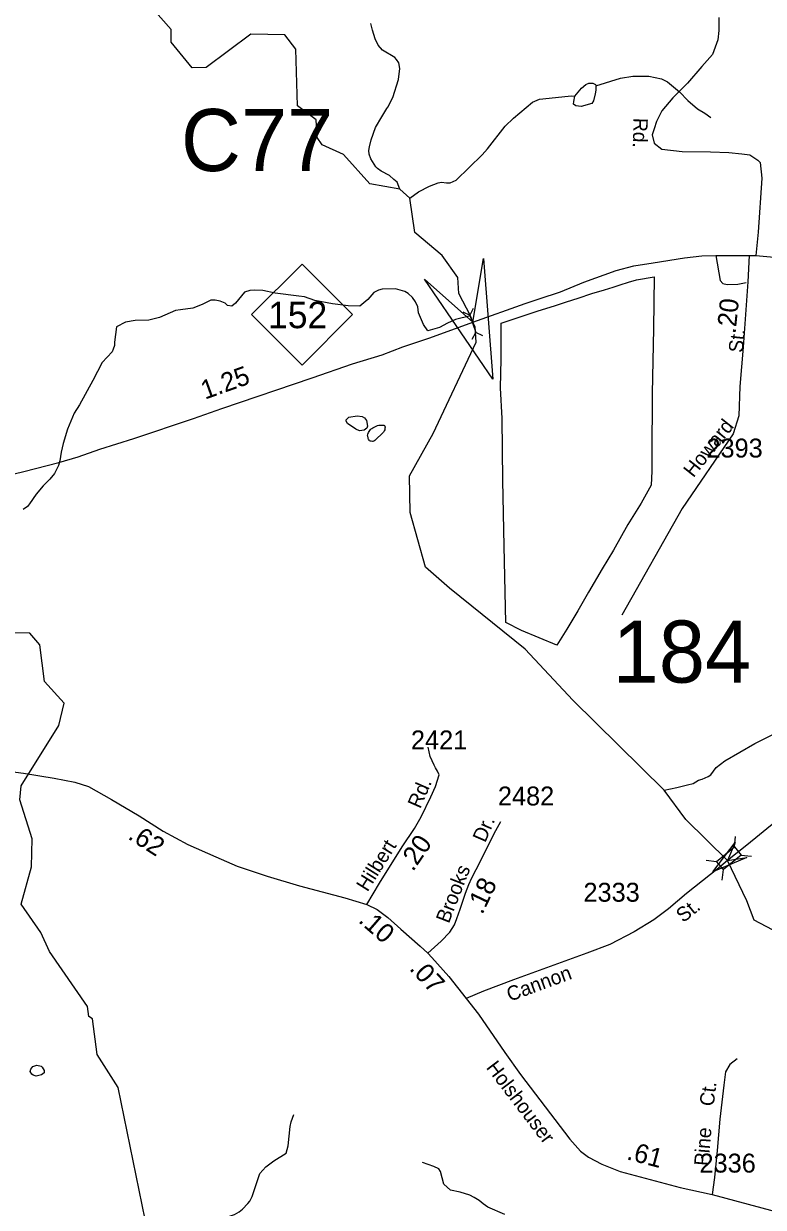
# Model space of a CAD drawing. Extents: x 1473865 to 1648260, y 639067 to 773536.
# Drawn here: x 1572849 to 1577734, y 652286 to 660104 of the extents above; entities that cross this region are included whole.
import ezdxf

# ---------------------------------------------------------------- set-up
doc = ezdxf.new("R2010")
doc.units = 0
for name, color, linetype in [('Exist Boundary Political City Limit New', 7, 'Continuous'), ('Exist Hydrographic Creek Single Shore', 7, 'Continuous'), ('Exist Hydrographic Misc Water Feature', 7, 'Continuous'), ('Exist Road Non-System Type 51', 7, 'Continuous'), ('Exist Road Non-System Type 51 Label', 7, 'Continuous'), ('Exist Road Primary NC Attributed', 7, 'Continuous'), ('Exist Road Primary NC Service Mileage Hundredths English Label', 7, 'Continuous'), ('Exist Road Primary NC Shield CELL', 7, 'Continuous'), ('Exist Road Primary NC Shield Number Label', 7, 'Continuous'), ('Exist Road Secondary Mileage Hundredths English Label', 7, 'Continuous'), ('Exist Road Secondary Structure Culvert Attributed CELL', 7, 'Continuous'), ('Exist Road Secondary Structure Culvert CELL', 7, 'Continuous'), ('Exist Road Secondary Structure Culvert Number Label', 7, 'Continuous'), ('Exist Road Secondary Structure Standard Bridge Attributed CELL', 7, 'Continuous'), ('Exist Road Secondary Structure Standard Bridge CELL', 7, 'Continuous'), ('Exist Road Secondary Structure Standard Bridge Number Label', 7, 'Continuous'), ('Exist Road Secondary Type 51 Attributed', 7, 'Continuous'), ('Exist Road Secondary Type 51 Label', 7, 'Continuous'), ('Exist Road Secondary Type 51 Number Label', 7, 'Continuous'), ('Map Preparation Boundary City Limit Buffer Line', 7, 'Continuous')]:
    doc.layers.add(name, color=color, linetype=linetype)

msp = doc.modelspace()

# ---------------------------------------------------------------- linework, layer by layer
at = {"layer": 'Exist Boundary Political City Limit New'}
msp.add_lwpolyline([(1576436.5, 656103.4), (1576371.1, 655999.6), (1576136.9, 656095.7), (1576033.1, 656149.5), (1576021.6, 656653), (1576014, 657087.4), (1576010.1, 657494.8), (1575998.6, 657698.5), (1576002.4, 657886.9), (1576002.4, 658125.1), (1576107.4, 658161.8), (1576247.6, 658206), (1576354.2, 658241.1), (1576433.5, 658265.7), (1576510.8, 658289.9), (1576601.6, 658320.5), (1576684.8, 658345.2), (1576741.8, 658362.4), (1576788.8, 658379.4), (1576844.2, 658396.6), (1576895.8, 658412.5), (1577012.6, 658432.6), (1577008.8, 658090.6), (1577001, 657660.1), (1576997.2, 657244.9), (1576997.2, 657148.9), (1576993.4, 657056.6), (1576928.1, 656937.4), (1576839.8, 656795.2), (1576743.8, 656626.1), (1576670.8, 656503.1), (1576578.5, 656349.4), (1576509.4, 656226.4), (1576436.5, 656103.4)], dxfattribs=at)
at = {"layer": 'Exist Hydrographic Creek Single Shore'}
msp.add_lwpolyline([(1577962.3, 654029.9), (1577674.3, 654182.5), (1577624.4, 654309.2), (1577496.8, 654576.7), (1577223.2, 654846.6), (1577078.6, 655040.2), (1576476.4, 655635.4), (1576161.4, 655973.1), (1575661, 656375.3), (1575503.4, 656513.3), (1575402.3, 656874.9), (1575398.3, 657117.9), (1575553.8, 657395.9), (1575837.4, 658000.3), (1575831.5, 658101.1), (1575814.9, 658133.1), (1575800.7, 658174.7), (1575723.3, 658322.5), (1575716.8, 658427.9), (1575613.1, 658573.2), (1575432.3, 658724.5), (1575398.4, 658950.1), (1575333.4, 659009.8), (1575134.4, 659046.7), (1574961.4, 659240.6), (1574821.4, 659302.5), (1574788.4, 659352.4), (1574781.4, 659467.4), (1574658.4, 659561.8), (1574646.4, 659936.2), (1574573.4, 660029.6), (1574348.4, 660034.2), (1574053.4, 659813.7), (1573961.4, 659812.2), (1573822.4, 659982.4), (1573823.4, 660064.5), (1573585.4, 660335.1)], dxfattribs=at)
at = {"layer": 'Exist Hydrographic Misc Water Feature'}
for points in [[(1575333.4, 659009.8), (1575316.5, 659057.3), (1575294.7, 659073.5), (1575265.9, 659099.9), (1575210.2, 659128.6), (1575186.4, 659146.9), (1575174.5, 659159), (1575141.1, 659211.4), (1575131.4, 659241.5), (1575129.6, 659265.6), (1575132, 659289.5), (1575144.5, 659337.4), (1575173.4, 659417), (1575214.2, 659488.6), (1575246.8, 659544.2), (1575254.9, 659552.1), (1575287.6, 659615.7), (1575324.9, 659735.3), (1575333.8, 659807.2), (1575326.2, 659845.3), (1575312.4, 659867.4), (1575300.5, 659879.6), (1575219, 659928.6), (1575189.4, 659960.9), (1575169.8, 660003.1), (1575152.5, 660061.3), (1575142.9, 660105.5)], [(1576629, 659694.1), (1576791.6, 659744.2), (1576871.7, 659757.3), (1576977.8, 659756.5), (1577061.6, 659739.1), (1577101.4, 659719), (1577180.8, 659653.7), (1577236.1, 659597), (1577299.5, 659540.3), (1577347.3, 659511.7), (1577386.9, 659483.3)], [(1576629, 659694.1), (1576628.7, 659664.1), (1576624.3, 659640.1), (1576611.8, 659594.3), (1576601.7, 659576.4), (1576531.5, 659557.3), (1576495.5, 659561.7), (1576481.5, 659571.8), (1576481.7, 659589.8), (1576488.2, 659625.7)], [(1576488.2, 659625.7), (1576532.8, 659677.3), (1576563, 659702.9), (1576581.2, 659710.7), (1576609.2, 659710.3), (1576625.1, 659702.2), (1576629, 659694.1)], [(1575398.4, 658950.1), (1575456.8, 658993.7), (1575529.3, 659030.9), (1575585.5, 659052.2), (1575609.5, 659056), (1575641.5, 659051.5), (1575665.5, 659053.3), (1575705.7, 659070.8), (1575877.7, 659236.8), (1575912.1, 659276.4), (1576029.8, 659427.1), (1576084.3, 659478.5), (1576209.6, 659585), (1576255.9, 659604.5), (1576277.9, 659608.2), (1576464.2, 659628), (1576488.2, 659625.7)], [(1575800.7, 658174.7), (1575701.1, 658149.7), (1575647.8, 658126), (1575594.4, 658096.4), (1575518.6, 658075), (1575490.5, 658117), (1575456.1, 658193.1), (1575453, 658233.7), (1575437.5, 658265.5), (1575417, 658294.1), (1575387.3, 658322.5), (1575365.4, 658334.7), (1575305.7, 658351.4), (1575217.6, 658350.4), (1575193.5, 658342.7), (1575161.3, 658327.1), (1575121.8, 658280.8), (1575068.3, 658238.2), (1574992.2, 658239.1), (1574888.4, 658252.3), (1574772.5, 658275.6), (1574702.8, 658298.4), (1574666.8, 658304.8), (1574509, 658324.7), (1574429.2, 658341.6), (1574373.1, 658343.9), (1574342.4, 658340.5), (1574307.9, 658329.4), (1574247.9, 658257.5), (1574222.9, 658238.7), (1574194.3, 658242.9), (1574179.1, 658258.3), (1574146.8, 658270.1), (1574114.4, 658278.2), (1574085.7, 658278.5), (1574028.1, 658248.6), (1573966.7, 658224.5), (1573883.8, 658213.7), (1573851.4, 658208.3), (1573747, 658163.6), (1573674.7, 658144.4), (1573584.7, 658144.2), (1573521.5, 658133.2), (1573462.1, 658100.9), (1573449, 658001), (1573448.8, 657977), (1573440.5, 657953.1), (1573432.3, 657937.2), (1573367.5, 657865.9), (1573306.2, 657746.6), (1573217.9, 657585.3), (1573181.7, 657530.1), (1573148.8, 657452.4), (1573138.6, 657424.6), (1573109.4, 657330.9), (1573096.8, 657273.1), (1573088.2, 657217.1), (1573079.8, 657185.3), (1573051.3, 657133.6), (1573021.9, 657096.2), (1572977.3, 657051.4), (1572931.7, 656995), (1572887, 656931.5), (1572874.8, 656915.6), (1572844.5, 656895.9)], [(1575051.3, 657513.2), (1575084.2, 657509.9), (1575100.1, 657499.8), (1575113.9, 657481.6), (1575119.5, 657445.5), (1575115.4, 657431.6), (1575097.2, 657417.8), (1575067.2, 657414.1), (1575043.3, 657424.4), (1574987.6, 657463.1), (1574977.8, 657479.2), (1574977.9, 657487.2), (1574996.1, 657504.9), (1575051.3, 657513.2)], [(1575144.9, 657345.3), (1575138.6, 657346.8), (1575133.2, 657348.6), (1575129.9, 657351.8), (1575126.8, 657358.9), (1575124.8, 657363.7), (1575123.1, 657368.6), (1575121.4, 657378.4), (1575120.7, 657383.9), (1575121.5, 657391.3), (1575126, 657403.4), (1575140.6, 657423.6), (1575143.7, 657426.9), (1575147.8, 657429.7), (1575154.8, 657434.4), (1575168.5, 657441.9), (1575186.8, 657450.2), (1575194.1, 657452.3), (1575205.3, 657452.4), (1575226.6, 657451.4), (1575233, 657449.6), (1575234.9, 657444.3), (1575235.7, 657438.1), (1575235.2, 657432.8), (1575234.1, 657422.1), (1575230.7, 657413.3), (1575228.6, 657409.5), (1575226, 657406.4), (1575168.9, 657350), (1575162.1, 657345.8), (1575155.8, 657344.9), (1575152.6, 657344.7), (1575144.9, 657345.3)], [(1573651.3, 652206.5), (1573472.3, 653076.7), (1573333.3, 653296.2), (1573303.3, 653529.9), (1573278.3, 653546.8), (1573271.3, 653612.5), (1573018.3, 653975.4), (1572961.3, 654101.3), (1572831.3, 654287.8), (1572901.3, 654535.8), (1572904.3, 654719.6), (1572824.3, 654977.2), (1572833.3, 655068.9), (1573081.4, 655467.6), (1573116.3, 655614.6), (1572985.3, 655758.5), (1572955.4, 656002), (1572890.3, 656078.8), (1572773.4, 656081.2), (1572363.4, 655977.8), (1572231.3, 656046.1), (1571977.4, 656349.9)], [(1577078.6, 655040.2), (1577162.6, 655059.7), (1577233, 655077.3), (1577270.1, 655085.1), (1577306.5, 655107.8), (1577330.5, 655113.6), (1577370.7, 655131.1), (1577386.8, 655142.9), (1577423.4, 655190.5), (1577479.9, 655233.8), (1577677.3, 655349.5), (1577806, 655412.1)], [(1572936.6, 653224.5), (1572963.9, 653218.3), (1572971.9, 653212.2), (1572983.5, 653190), (1572983.4, 653174), (1572967.2, 653160.2), (1572931.2, 653152.7), (1572911.2, 653158.9), (1572903.3, 653165), (1572891.5, 653183.1), (1572895.7, 653199.1), (1572909.8, 653214.9), (1572936.6, 653224.5)], [(1573758, 651873.6), (1573849.7, 651907.8), (1573914.1, 651939.1), (1573944.4, 651968.7), (1573975.1, 652022.4), (1574003.5, 652062.1), (1574132.9, 652184.6), (1574189.3, 652219.9), (1574241.5, 652239.3), (1574271.7, 652256.9), (1574293.9, 652272.7), (1574330.3, 652310.3), (1574342.5, 652326.1), (1574358.9, 652357.9), (1574407.7, 652508.9), (1574448.2, 652553.4), (1574500.6, 652591.9), (1574582.1, 652643.4), (1574596.7, 652691.2), (1574608.1, 652819.1), (1574616.5, 652851), (1574633, 652898.8)], [(1576026.2, 652238.5), (1575914.7, 652287.9), (1575882.9, 652308.2), (1575857.1, 652330.5), (1575825.4, 652350.9), (1575795.5, 652365.2), (1575732.1, 652386), (1575667.8, 652398.7), (1575624.2, 652439.2), (1575601.1, 652523.5), (1575591.4, 652539.6), (1575557.6, 652556), (1575483.7, 652582.9)]]:
    msp.add_lwpolyline(points, dxfattribs=at)
at = {"layer": 'Exist Road Non-System Type 51'}
for points in [[(1577419.5, 658571.9), (1577448.1, 658407.4), (1577465.8, 658388.5), (1577494.6, 658380.9), (1577566.1, 658382.4), (1577620.7, 658395.1)], [(1577573, 657512.9), (1577536, 657393.7), (1577197.1, 656900.8), (1576799.3, 656196.2)], [(1575559.7, 655206.3), (1575532.9, 655262.4), (1575519.4, 655324.5)], [(1577562, 653266.5), (1577513.8, 653229), (1577485.4, 653181.2), (1577472.6, 653093.2), (1577446.8, 652867.4), (1577429.3, 652661.5), (1577411.9, 652483.5), (1577397, 652369.6)]]:
    msp.add_lwpolyline(points, dxfattribs=at)
at = {"layer": 'Exist Road Primary NC Attributed'}
for points in [[(1572646.5, 657097.5), (1572850.9, 657145.8), (1573081.4, 657205.8), (1573209.8, 657242.8), (1573352.1, 657293.6), (1573576.9, 657363.7), (1573969.9, 657496.4), (1574156.6, 657562.9), (1574754.3, 657763.9), (1575021.1, 657857.8), (1575215.6, 657916.1), (1575352.1, 657968.9), (1575530.6, 658029.6), (1575814.9, 658133.1), (1576160.7, 658254.4), (1576253.1, 658286.6), (1576394.1, 658333.1), (1576548.3, 658396.6), (1576761.9, 658472.3), (1576878.4, 658503.4), (1577006.6, 658524.8), (1577214.3, 658557.8), (1577327, 658569.4), (1577419.5, 658571.9), (1577641.5, 658573)], [(1577641.5, 658573), (1577685.3, 658573.2)], [(1577685.3, 658573.2), (1577877.7, 658555.8), (1578045.6, 658554.7), (1578207.5, 658547.2), (1578374, 658540.7)]]:
    msp.add_lwpolyline(points, dxfattribs=at)
at = {"layer": 'Exist Road Primary NC Shield CELL'}
msp.add_lwpolyline([(1574354.2, 658182), (1574687.2, 658515), (1575020.2, 658182), (1574687.2, 657849.1)], close=True, dxfattribs=at)
at = {"layer": 'Exist Road Secondary Structure Culvert Attributed CELL'}
msp.add_lwpolyline([(1575886.8, 658553.4), (1575947.4, 657755.7), (1575496.1, 658416.3), (1575814.9, 658133.1)], close=True, dxfattribs=at)
at = {"layer": 'Exist Road Secondary Structure Culvert CELL'}
for p, q in [((1575749, 658199.3), (1575795.2, 658178.3)), ((1575818.8, 658223.3), (1575795.2, 658178.3)), ((1575795.2, 658178.3), (1575834.5, 658063.9)), ((1575811, 658018.9), (1575834.5, 658063.9)), ((1575880.7, 658042.9), (1575834.5, 658063.9))]:
    msp.add_line(p, q, dxfattribs=at)
at = {"layer": 'Exist Road Secondary Structure Standard Bridge Attributed CELL'}
msp.add_lwpolyline([(1577625.2, 654596.9), (1577400.7, 654501.7), (1577547.5, 654696.4), (1577496.8, 654576.7)], close=True, dxfattribs=at)
at = {"layer": 'Exist Road Secondary Structure Standard Bridge CELL'}
for p, q in [((1577543.1, 654665.9), (1577550.1, 654734.5)), ((1577586.7, 654612.4), (1577655.3, 654605.4)), ((1577357.1, 654577.7), (1577425.8, 654570.7)), ((1577463.3, 654447.4), (1577470.3, 654516))]:
    msp.add_line(p, q, dxfattribs=at)
msp.add_lwpolyline([(1577425.8, 654570.7), (1577542.9, 654666.2), (1577587.5, 654611.4), (1577470.3, 654516)], close=True, dxfattribs=at)
at = {"layer": 'Exist Road Secondary Type 51 Attributed'}
for points in [[(1577439.6, 660144.7), (1577439.6, 660059.2), (1577433.8, 659997.1), (1577398.8, 659900), (1577328.9, 659820.3), (1577234.3, 659709.8), (1577137.5, 659612.7), (1577064.8, 659528), (1577027.9, 659458.1), (1577012.4, 659409.5), (1577000.8, 659368.7), (1577012.4, 659314.3), (1577064.8, 659275.5), (1577198.8, 659259.9), (1577385.8, 659258.2), (1577506.8, 659251.7), (1577593, 659244.4), (1577644.5, 659236.3), (1577699, 659202), (1577713.1, 659187.4), (1577725.4, 659082.2), (1577699.7, 658726.9), (1577685.3, 658573.2)], [(1577641.5, 658573), (1577631.8, 658398.5), (1577601.8, 657966.1), (1577579.8, 657708), (1577573, 657512.9)], [(1578879.5, 656877.8), (1578867.8, 656775), (1578818.9, 656641.3), (1578731.6, 656490), (1578632.9, 656312.9), (1578604.5, 656260.7), (1578562.6, 656192.6), (1578533.2, 656140.1), (1578497.6, 656068.9), (1578376.6, 655862.7), (1578265.1, 655663.6), (1578198.1, 655556.1), (1578155.6, 655482.4), (1578136.3, 655320.5), (1578137.6, 655226.4), (1578116.9, 655150.6), (1578049.8, 655046), (1577924.7, 654922.8), (1577625.7, 654678.4), (1577496.8, 654576.7)], [(1572043.8, 655318.8), (1572101.7, 655287.8), (1572163.5, 655265.3), (1572291.7, 655237.8), (1572593.4, 655187.1), (1572847.3, 655153), (1573049.1, 655121.3), (1573187.6, 655093.4), (1573277.7, 655064.9), (1573428.3, 654979.2), (1573611.6, 654871.6), (1573771, 654770.6), (1573932.2, 654682.8), (1574118.4, 654600.3), (1574258.9, 654539), (1574457.5, 654472.1), (1574670.1, 654409.4), (1574969.5, 654330.3), (1575115.2, 654285.6)], [(1575115.2, 654285.6), (1575198.3, 654427), (1575348.2, 654665.8), (1575431.3, 654787), (1575473.9, 654864.8), (1575539, 654996.4), (1575569.4, 655066), (1575592.1, 655141.9), (1575582.2, 655166), (1575568.4, 655188), (1575559.7, 655206.3)], [(1575519, 653963.9), (1575605.5, 654044.2), (1575663.1, 654103.9), (1575694, 654151.2), (1575710.5, 654194.4), (1575731, 654256.2), (1575768.1, 654361.2), (1575788.7, 654418.8), (1575809.3, 654462), (1575866.9, 654573.2), (1575957.5, 654754.3), (1575978, 654795.4), (1575999.4, 654834)], [(1577496.8, 654576.7), (1577438.1, 654525.8), (1577227.1, 654357.7), (1577107.9, 654257.9), (1577012.1, 654185.6), (1576880.8, 654105.9), (1576720, 654021.3), (1576568.2, 653965.3), (1576084.8, 653787.4), (1575885, 653713), (1575770.6, 653665.8)], [(1575115.2, 654285.6), (1575183.5, 654252.1), (1575253.5, 654200.6), (1575340, 654122.4), (1575467.6, 654011.2), (1575519, 653963.9)], [(1575519, 653963.9), (1575545.8, 653935.1), (1575657.7, 653810.8), (1575770.6, 653665.8)], [(1575770.6, 653665.8), (1575853.7, 653561.1), (1576025.9, 653307.5), (1576130.8, 653162.5), (1576455.5, 652735.6), (1576527, 652657.1), (1576578.6, 652616.6), (1576668.3, 652569.8), (1576788, 652522.8), (1577185.2, 652417.5), (1577397, 652369.6), (1577962, 652218.7), (1578155.4, 652157.2), (1578365.8, 652079.1)]]:
    msp.add_lwpolyline(points, dxfattribs=at)
at = {"layer": 'Map Preparation Boundary City Limit Buffer Line'}
msp.add_lwpolyline([(1576436.5, 656103.4), (1576371.1, 655999.6), (1576136.9, 656095.7), (1576033.1, 656149.5), (1576021.6, 656653), (1576014, 657087.4), (1576010.1, 657494.8), (1575998.6, 657698.5), (1576002.4, 657886.9), (1576002.4, 658125.1), (1576107.4, 658161.8), (1576247.6, 658206), (1576354.2, 658241.1), (1576433.5, 658265.7), (1576510.8, 658289.9), (1576601.6, 658320.5), (1576684.8, 658345.2), (1576741.8, 658362.4), (1576788.8, 658379.4), (1576844.2, 658396.6), (1576895.8, 658412.5), (1577012.6, 658432.6), (1577008.8, 658090.6), (1577001, 657660.1), (1576997.2, 657244.9), (1576997.2, 657148.9), (1576993.4, 657056.6), (1576928.1, 656937.4), (1576839.8, 656795.2), (1576743.8, 656626.1), (1576670.8, 656503.1), (1576578.5, 656349.4), (1576509.4, 656226.4), (1576436.5, 656103.4)], dxfattribs=at)

# ---------------------------------------------------------------- texts
at = {"layer": 'Exist Road Non-System Type 51 Label'}
for s, rotation, p in [('St.', 84.26262, (1577598.4, 657927.4)), ('Howard', 51.47961, (1577272.2, 657100.6)), ('Ct.', 83.48853, (1577406.8, 652950.2)), ('Pine', 85.12398, (1577371, 652556.7))]:
    msp.add_text(s, height=95, rotation=rotation, dxfattribs=at).set_placement(p)
at = {"layer": 'Exist Road Primary NC Service Mileage Hundredths English Label'}
msp.add_text('1.25', height=125, rotation=19.60314, dxfattribs=at).set_placement((1574046.4, 657620))
at = {"layer": 'Exist Road Primary NC Shield Number Label'}
msp.add_text('152', height=175, dxfattribs=at).set_placement((1574463.3, 658092.3))
at = {"layer": 'Exist Road Secondary Mileage Hundredths English Label'}
for s, rotation, p in [('.20', 84.26262, (1577550.4, 658051.4)), ('.62', 327.57641, (1573531.2, 654723.5)), ('.20', 55.56361, (1575419.6, 654498.5)), ('.18', 64.53665, (1575878, 654214.6)), ('.10', 318.96077, (1575053.5, 654173.5)), ('.07', 312.60306, (1575391.3, 653859.4)), ('.61', 345.15845, (1576825.9, 652604))]:
    msp.add_text(s, height=125, rotation=rotation, dxfattribs=at).set_placement(p)
at = {"layer": 'Exist Road Secondary Structure Culvert Number Label'}
msp.add_text('C77', height=410.1, dxfattribs=at).set_placement((1573887.7, 659130))
at = {"layer": 'Exist Road Secondary Structure Standard Bridge Number Label'}
msp.add_text('184', height=410.1, dxfattribs=at).set_placement((1576739.1, 655751.3))
at = {"layer": 'Exist Road Secondary Type 51 Label'}
for s, rotation, p in [('Rd.', 268.52429, (1576876.9, 659482.1)), ('Rd.', 66.39726, (1575467.9, 654914)), ('Dr.', 66.39726, (1575897.1, 654689.8)), ('Hilbert', 57.8933, (1575119.6, 654364.8)), ('Brooks', 68.59465, (1575656.7, 654156)), ('St.', 38.57034, (1577205.4, 654162.4)), ('Cannon', 20.20659, (1576059.6, 653643.4)), ('Holshouser', 307.25545, (1575899.6, 653208.2))]:
    msp.add_text(s, height=95, rotation=rotation, dxfattribs=at).set_placement(p)
at = {"layer": 'Exist Road Secondary Type 51 Number Label'}
for s, p in [('2393', (1577358.4, 657238.1)), ('2421', (1575406.8, 655310.4)), ('2482', (1575981.1, 654940)), ('2333', (1576546.2, 654304.3)), ('2336', (1577312.7, 652515.3))]:
    msp.add_text(s, height=125, dxfattribs=at).set_placement(p)

doc.saveas('drawing.dxf')
